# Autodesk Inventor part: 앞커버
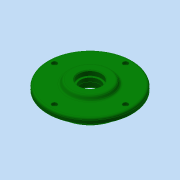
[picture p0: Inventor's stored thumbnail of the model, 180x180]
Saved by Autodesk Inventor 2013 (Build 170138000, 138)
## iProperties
Created: 2016-11
Part Number: 앞커버
Material: 알루미늄 6061
Document SubType Name: Modeling
Designer: mduedu
Density: 1 g/cm^3
Author: mduedu
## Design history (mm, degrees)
sketch "스케치1"
  geometry: L1 (28.5, -17.5)-(28.5, -30); L2 (28.5, -30)-(22.5, -33.464); L3 (22.5, -33.464)-(22.5, -65); L4 (22.5, -65)-(14.5, -65); L5 (14.5, -65)-(14.5, -47.5); L6 (14.5, -47.5)-(0, -47.5); L7 (0, -47.5)-(0, -23.5); L8 (0, 0)-(28.5, 0); L9 (14.5, -23.5)-(14.5, -15); L10 (14.5, -15)-(20.5, -15); L11 (20.5, -15)-(20.5, -17.5); L12 (0, -23.5)-(14.5, -23.5); L13 (20.5, -17.5)-(28.5, -17.5)
  constraints: 26 end point, 8 parallel, 3 perpendicular, 2 horizontal, 2 vertical alignment, 1 collinear
  dimensions: "d0" = 14.5 distance of L5.end L6.end; "d2" = 8 distance of L3.end L4.end; "d3" = 6 distance between parallel lines of L1 L3; "d4" = 120 deg angle of L3 L2; "d5" = 8 distance of L11.end L1.start; "d6" = 60 diameter of L1.end L8; "d7" = 30 diameter of L10 L8; "d8" = 47 diameter of L12 L8; "d9" = 35 diameter of L13 L8; "d10" = 95 diameter of L6 L8; "d11" = 130 diameter of L4 L8
revolve "회전1" sketch "스케치1" stored, may be unused: angle "d12" = 90 deg
fillet "모깎기1" dims "d13" = 0.5
fillet "모깎기2" dims "d14" = 3
chamfer "모따기1" distance "d15" = 1; stored, may be unused: second distance "d16" = 2, angle "d17" = 45 deg
fillet "모깎기3" dims "d18" = 0.3
sketch "스케치2" dims "d19" = 110
  geometry: 6 further points
  constraints: 2 vertical alignment, 1 coincident, 7 other
  dimensions: "d22" = 360 deg dimension on point (0, 0) point (0, 55) (derived)
sketch "스케치3"
  geometry: 4 further points
  constraints: 4 other
hole "구멍1" sketch "스케치3" at (0, 55), (-55, 0), (55, 0), (0, -55) diameter "d24" = 4.5; stored, may be unused: countersink angle "d28" = 90 deg, drill point angle "d30" = 0 deg; dims "d25" = 6, "d26" = 8, "d27" = 4.6, "d29" = 8
node "솔리드1"
